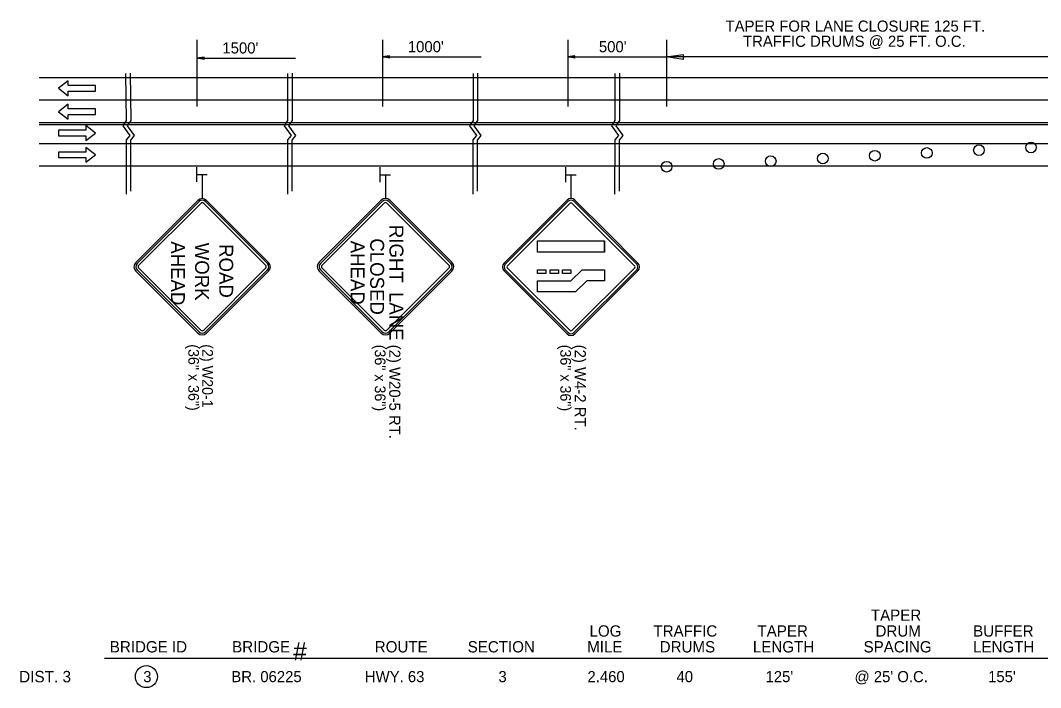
# Model space of a CAD drawing. Extents: x 1930579 to 1937984, y 596452 to 597630.
# Drawn here: x 1936443 to 1936993, y 596780 to 597140 of the extents above; entities that cross this region are included whole.
import ezdxf

# ---------------------------------------------------------------- set-up
doc = ezdxf.new("R2010")
doc.units = 0
for name, color, linetype in [('Default', 7, 'Continuous'), ('P_TC_Signs_Permanent', 7, 'Continuous'), ('P_TC_Signs_Temporary', 7, 'Continuous'), ('R_Annotation', 7, 'Continuous'), ('R_Striping', 7, 'Continuous')]:
    doc.layers.add(name, color=color, linetype=linetype)

msp = doc.modelspace()

# ---------------------------------------------------------------- linework, layer by layer
at = {"layer": 'Default'}
for p, q in [((1936537.79, 597129.19), (1936537.79, 597093.28)), ((1936637.79, 597129.19), (1936637.79, 597093.28)), ((1936737.79, 597129.19), (1936737.79, 597093.28)), ((1936791.02, 597129.19), (1936791.02, 597093.28)), ((1936541.62, 597119.78), (1936537.79, 597119.21)), ((1936537.79, 597119.21), (1936591.02, 597119.21)), ((1936541.62, 597118.63), (1936537.79, 597119.21)), ((1936541.62, 597119.68), (1936538.43, 597119.21)), ((1936541.62, 597118.73), (1936538.43, 597119.21)), ((1936541.62, 597119.59), (1936539.09, 597119.21)), ((1936541.62, 597118.83), (1936539.09, 597119.21)), ((1936541.62, 597119.49), (1936539.73, 597119.21)), ((1936541.62, 597118.92), (1936539.73, 597119.21)), ((1936541.62, 597119.39), (1936540.37, 597119.21)), ((1936541.62, 597119.02), (1936540.37, 597119.21)), ((1936541.62, 597119.3), (1936541.01, 597119.21)), ((1936541.62, 597119.12), (1936541.01, 597119.21)), ((1936541.62, 597118.63), (1936541.62, 597119.78)), ((1936641.62, 597120.46), (1936637.79, 597119.89)), ((1936637.79, 597119.89), (1936691.02, 597119.89)), ((1936641.62, 597119.31), (1936637.79, 597119.89)), ((1936641.62, 597120.36), (1936638.43, 597119.89)), ((1936641.62, 597119.41), (1936638.43, 597119.89)), ((1936641.62, 597120.27), (1936639.09, 597119.89)), ((1936641.62, 597119.51), (1936639.09, 597119.89)), ((1936641.62, 597120.17), (1936639.73, 597119.89)), ((1936641.62, 597119.6), (1936639.73, 597119.89)), ((1936641.62, 597120.07), (1936640.37, 597119.89)), ((1936641.62, 597119.7), (1936640.37, 597119.89)), ((1936641.62, 597119.98), (1936641.01, 597119.89)), ((1936641.62, 597119.8), (1936641.01, 597119.89)), ((1936641.62, 597119.31), (1936641.62, 597120.46)), ((1936741.62, 597120.46), (1936737.79, 597119.89)), ((1936737.79, 597119.89), (1936791.02, 597119.89)), ((1936741.62, 597119.31), (1936737.79, 597119.89)), ((1936741.62, 597120.36), (1936738.43, 597119.89)), ((1936741.62, 597119.41), (1936738.43, 597119.89)), ((1936741.62, 597120.27), (1936739.09, 597119.89)), ((1936741.62, 597119.51), (1936739.09, 597119.89)), ((1936741.62, 597120.17), (1936739.73, 597119.89)), ((1936741.62, 597119.6), (1936739.73, 597119.89)), ((1936741.62, 597120.07), (1936740.37, 597119.89)), ((1936741.62, 597119.7), (1936740.37, 597119.89)), ((1936741.62, 597119.98), (1936741.01, 597119.89)), ((1936741.62, 597119.8), (1936741.01, 597119.89)), ((1936741.62, 597119.31), (1936741.62, 597120.46)), ((1936791.02, 597119.89), (1936799.89, 597121.22)), ((1937015.53, 597119.89), (1936791.02, 597119.89)), ((1936799.89, 597118.56), (1936791.02, 597119.89)), ((1936799.89, 597121.22), (1936799.89, 597118.56)), ((1937804.86, 597108.65), (1936452.69, 597108.65)), ((1937804.86, 597096.65), (1936452.69, 597096.65)), ((1937804.86, 597084.42), (1936452.69, 597084.42)), ((1937804.86, 597083.27), (1936452.69, 597083.27)), ((1937804.86, 597073.09), (1936452.69, 597073.09)), ((1937804.86, 597061.09), (1936452.69, 597061.09)), ((1936537.79, 597052.49), (1936537.79, 597060.47)), ((1936636.62, 597052.43), (1936636.62, 597060.41)), ((1936736.62, 597052.43), (1936736.62, 597060.41)), ((1936537.91, 597056.46), (1936543.36, 597056.46)), ((1936636.74, 597056.4), (1936642.18, 597056.4)), ((1936736.74, 597056.4), (1936742.18, 597056.4))]:
    msp.add_line(p, q, dxfattribs=at)
for points in [[(1936499.33, 597110.93), (1936499.72, 597085.69), (1936497.77, 597082.8), (1936501.57, 597077.6), (1936499.57, 597075.2), (1936499.56, 597045.85)], [(1936501.73, 597111.16), (1936502.12, 597085.59), (1936500.17, 597082.7), (1936503.96, 597077.5), (1936501.96, 597075.1), (1936501.96, 597047.54)], [(1936586.69, 597110.93), (1936586.69, 597085.69), (1936584.74, 597082.8), (1936588.54, 597077.6), (1936586.54, 597075.2), (1936586.54, 597045.85)], [(1936589.09, 597111.16), (1936589.09, 597085.59), (1936587.14, 597082.7), (1936590.94, 597077.5), (1936588.94, 597075.1), (1936588.94, 597047.54)], [(1936686.69, 597110.93), (1936686.69, 597085.69), (1936684.74, 597082.8), (1936688.54, 597077.6), (1936686.54, 597075.2), (1936686.54, 597045.85)], [(1936689.09, 597111.16), (1936689.09, 597085.59), (1936687.14, 597082.7), (1936690.94, 597077.5), (1936688.94, 597075.1), (1936688.94, 597047.54)], [(1936763.16, 597110.93), (1936763.16, 597085.69), (1936761.21, 597082.8), (1936765.01, 597077.6), (1936763.01, 597075.2), (1936763, 597045.85)], [(1936765.56, 597111.16), (1936765.56, 597085.59), (1936763.61, 597082.7), (1936767.4, 597077.5), (1936765.41, 597075.1), (1936765.4, 597047.54)]]:
    msp.add_lwpolyline(points, dxfattribs=at)
for centre, radius in [((1936903.28, 597066.66), 2.87), ((1936931.34, 597068.14), 2.87), ((1936959.4, 597069.63), 2.87), ((1936987.47, 597071.11), 2.87), ((1936819.09, 597062.2), 2.87), ((1936847.15, 597063.68), 2.87), ((1936875.21, 597065.17), 2.87), ((1936791.02, 597060.71), 2.87), ((1936510.53, 596785.7), 5.92)]:
    msp.add_circle(centre, radius, dxfattribs=at)
at = {"layer": 'P_TC_Signs_Permanent'}
for p, q in [((1936703.4, 597008.78), (1936737.34, 597042.72)), ((1936757.46, 597014.7), (1936757.46, 597020.7)), ((1936737.34, 596970.6), (1936703.4, 597004.54)), ((1936775.52, 597004.54), (1936741.58, 596970.6))]:
    msp.add_line(p, q, dxfattribs=at)
for points in [[(1936737.97, 597042.08), (1936704.03, 597008.14)], [(1936774.89, 597008.14), (1936740.94, 597042.08)], [(1936741.58, 597042.72), (1936758.55, 597025.75), (1936775.52, 597008.78)], [(1936705.09, 597007.08), (1936739.04, 597041.02)], [(1936739.88, 597041.02), (1936773.82, 597007.08)], [(1936704.03, 597005.17), (1936737.97, 596971.23)], [(1936739.04, 596972.29), (1936705.09, 597006.23)], [(1936773.82, 597006.23), (1936739.88, 596972.29)], [(1936740.94, 596971.23), (1936774.89, 597005.17)]]:
    msp.add_lwpolyline(points, dxfattribs=at)
for points in [[(1936721.46, 597014.7), (1936721.46, 597020.7), (1936757.46, 597020.7), (1936757.46, 597014.7)], [(1936721.46, 597003.06), (1936721.46, 597005.16), (1936725.96, 597005.16), (1936725.96, 597003.06)], [(1936721.46, 596993.16), (1936721.46, 596999.16), (1936739.46, 596999.16), (1936745.46, 597005.16), (1936757.46, 597005.16), (1936757.46, 596999.16), (1936747.94, 596999.16), (1936741.94, 596993.16)], [(1936728.21, 597003.06), (1936728.21, 597005.16), (1936732.71, 597005.16), (1936732.71, 597003.06)], [(1936734.96, 597003.06), (1936734.96, 597005.16), (1936739.46, 597005.16), (1936739.46, 597003.06)]]:
    msp.add_lwpolyline(points, close=True, dxfattribs=at)
for centre, radius, start, end in [((1936739.46, 597040.6), 3, 45, 135), ((1936739.46, 597040.6), 2.1, 45, 135), ((1936739.46, 597040.6), 0.6, 45, 135), ((1936705.52, 597006.66), 3, 135, 225), ((1936773.4, 597006.66), 3, 315, 45), ((1936705.52, 597006.66), 2.1, 135, 225), ((1936705.52, 597006.66), 0.6, 135, 225), ((1936773.4, 597006.66), 0.6, 315, 45), ((1936773.4, 597006.66), 2.1, 315, 45), ((1936739.46, 596972.72), 3, 225, 315), ((1936739.46, 596972.72), 2.1, 225, 315), ((1936739.46, 596972.72), 0.6, 225, 315)]:
    msp.add_arc(centre, radius, start, end, dxfattribs=at)
at = {"layer": 'P_TC_Signs_Temporary'}
for p, q in [((1936504.84, 597009.13), (1936538.25, 597042.54)), ((1936505.5, 597008.46), (1936538.91, 597041.88)), ((1936542.36, 597041.88), (1936575.77, 597008.46)), ((1936543.02, 597042.54), (1936576.43, 597009.13)), ((1936603.66, 597009.2), (1936637.07, 597042.61)), ((1936604.33, 597008.54), (1936637.74, 597041.95)), ((1936641.18, 597041.95), (1936674.59, 597008.54)), ((1936641.85, 597042.61), (1936675.26, 597009.2)), ((1936506.43, 597007.54), (1936539.84, 597040.95)), ((1936541.43, 597040.95), (1936574.84, 597007.54)), ((1936605.25, 597007.61), (1936638.66, 597041.02)), ((1936640.26, 597041.02), (1936673.67, 597007.61)), ((1936538.25, 596970.94), (1936504.84, 597004.35)), ((1936538.91, 596971.61), (1936505.5, 597005.02)), ((1936539.84, 596972.53), (1936506.43, 597005.95)), ((1936574.84, 597005.95), (1936541.43, 596972.53)), ((1936575.77, 597005.02), (1936542.36, 596971.61)), ((1936576.43, 597004.35), (1936543.02, 596970.94)), ((1936637.07, 596971.02), (1936603.66, 597004.43)), ((1936637.74, 596971.68), (1936604.33, 597005.09)), ((1936638.66, 596972.61), (1936605.25, 597006.02)), ((1936673.67, 597006.02), (1936640.26, 596972.61)), ((1936674.59, 597005.09), (1936641.18, 596971.68)), ((1936675.26, 597004.43), (1936641.85, 596971.02))]:
    msp.add_line(p, q, dxfattribs=at)
for centre, radius, start, end in [((1936540.63, 597040.15), 3.38, 45, 135), ((1936540.63, 597040.15), 2.44, 45, 135), ((1936639.46, 597040.22), 3.38, 45, 135), ((1936639.46, 597040.22), 2.44, 45, 135), ((1936540.63, 597040.15), 1.12, 45, 135), ((1936639.46, 597040.22), 1.12, 45, 135), ((1936507.22, 597006.74), 3.38, 135, 225), ((1936574.04, 597006.74), 3.38, 315, 45), ((1936606.05, 597006.81), 3.38, 135, 225), ((1936672.87, 597006.81), 3.38, 315, 45), ((1936507.22, 597006.74), 2.44, 135, 225), ((1936507.22, 597006.74), 1.13, 135, 225), ((1936574.04, 597006.74), 1.13, 315, 45), ((1936574.04, 597006.74), 2.44, 315, 45), ((1936606.05, 597006.81), 2.44, 135, 225), ((1936606.05, 597006.81), 1.13, 135, 225), ((1936672.87, 597006.81), 1.13, 315, 45), ((1936672.87, 597006.81), 2.44, 315, 45), ((1936540.63, 596973.33), 3.38, 225, 315), ((1936540.63, 596973.33), 2.44, 225, 315), ((1936540.63, 596973.33), 1.12, 225, 315), ((1936639.46, 596973.4), 3.38, 225, 315), ((1936639.46, 596973.4), 2.44, 225, 315), ((1936639.46, 596973.4), 1.12, 225, 315)]:
    msp.add_arc(centre, radius, start, end, dxfattribs=at)
at = {"layer": 'R_Annotation'}
for p, q in [((1936540.63, 597056.46), (1936540.63, 597043.53)), ((1936639.46, 597056.4), (1936639.46, 597043.6)), ((1936739.46, 597056.4), (1936739.46, 597043.6)), ((1936487.9, 596795.58), (1937056.56, 596795.58))]:
    msp.add_line(p, q, dxfattribs=at)
at = {"layer": 'R_Striping'}
for points in [[(1936468.42, 597107.02), (1936463.23, 597103.02), (1936468.42, 597099.02), (1936468.42, 597101.52), (1936483.13, 597101.52), (1936483.13, 597104.52), (1936468.42, 597104.52)], [(1936468.42, 597094.38), (1936463.23, 597090.38), (1936468.42, 597086.38), (1936468.42, 597088.88), (1936483.13, 597088.88), (1936483.13, 597091.88), (1936468.42, 597091.88)], [(1936477.94, 597074.88), (1936483.13, 597078.88), (1936477.94, 597082.88), (1936477.94, 597080.38), (1936463.23, 597080.38), (1936463.23, 597077.38), (1936477.94, 597077.38)], [(1936477.94, 597063.1), (1936483.13, 597067.1), (1936477.94, 597071.1), (1936477.94, 597068.6), (1936463.23, 597068.6), (1936463.23, 597065.6), (1936477.94, 597065.6)]]:
    msp.add_lwpolyline(points, close=True, dxfattribs=at)

# ---------------------------------------------------------------- texts
at = {"layer": 'Default'}
for s, p in [('TAPER FOR LANE CLOSURE 125 FT.', (1936822.78, 597133.54)), ('TRAFFIC DRUMS @ 25 FT. O.C.', (1936832.22, 597125.38)), ("1500'", (1936551.51, 597121.78)), ("1000'", (1936651.51, 597122.45)), ("500'", (1936754.51, 597122.45))]:
    msp.add_text(s, height=6, rotation=360, dxfattribs=at).set_placement(p)
at = {"layer": 'P_TC_Signs_Temporary'}
for s, p in [('RIGHT\u2002LANE', (1936641.59, 597029.33)), (' AHEAD ', (1936523.8, 597023.28)), ('WORK', (1936536.82, 597019.73)), (' AHEAD ', (1936620.71, 597023.59)), ('CLOSED', (1936631.21, 597022.07)), (' ROAD ', (1936549.85, 597021.76))]:
    msp.add_text(s, height=7.5, rotation=270, dxfattribs=at).set_placement(p)
at = {"layer": 'R_Annotation'}
for s, height, rotation, p in [('(36" x 36")', 5.76, 270, (1936533.14, 596964.96)), ('(2) W20-1', 5.76, 270, (1936540.63, 596964.96)), ('(36" x 36")', 5.76, 270, (1936633.7, 596964.72)), ('(2) W20-5 RT.', 6, 270, (1936641.47, 596964.72)), ('(36" x 36")', 5.76, 270, (1936733.7, 596964.72)), ('(2) W4-2 RT.', 6, 270, (1936741.47, 596964.72)), ('TAPER', 6.094, 360, (1936901.13, 596815.8)), ('LOG', 6.094, 360, (1936749.45, 596807.27)), ('TRAFFIC', 6.094, 360, (1936783.91, 596807.27)), ('TAPER', 6.094, 360, (1936840, 596807.27)), ('DRUM', 6.094, 360, (1936903.65, 596807.27)), ('BUFFER', 6.094, 360, (1936956.26, 596807.27)), ('BRIDGE ID', 6.094, 360, (1936490.83, 596798.74)), ('BRIDGE ', 6.094, 360, (1936556.78, 596798.74)), ('#', 9.75, 360, (1936589.71, 596794.43)), ('ROUTE', 6.094, 360, (1936633.66, 596798.74)), ('SECTION', 6.094, 360, (1936683.76, 596798.74)), ('MILE', 6.094, 360, (1936748.18, 596798.74)), ('DRUMS', 6.094, 360, (1936787.29, 596798.74)), ('LENGTH', 6.094, 360, (1936837.53, 596798.74)), ('SPACING', 6.094, 360, (1936897.2, 596798.74)), ('LENGTH', 6.094, 360, (1936956.24, 596798.74)), ('DIST. 3', 6.171, 360, (1936441.94, 596782.61)), ('3', 6, 360, (1936508.83, 596782.7)), ('BR. 06225', 6, 360, (1936556.34, 596782.7)), ('HWY. 63', 6, 360, (1936628.34, 596782.7)), ('3', 6, 360, (1936700.34, 596782.7)), ('2.460', 6, 360, (1936748.34, 596782.7)), ('40', 6, 360, (1936796.34, 596782.7)), ("125'", 6, 360, (1936844.34, 596782.7)), ("@ 25' O.C.", 6, 360, (1936892.34, 596782.7)), ("155'", 6, 360, (1936964.34, 596782.7))]:
    msp.add_text(s, height=height, rotation=rotation, dxfattribs=at).set_placement(p)

doc.saveas('drawing.dxf')
